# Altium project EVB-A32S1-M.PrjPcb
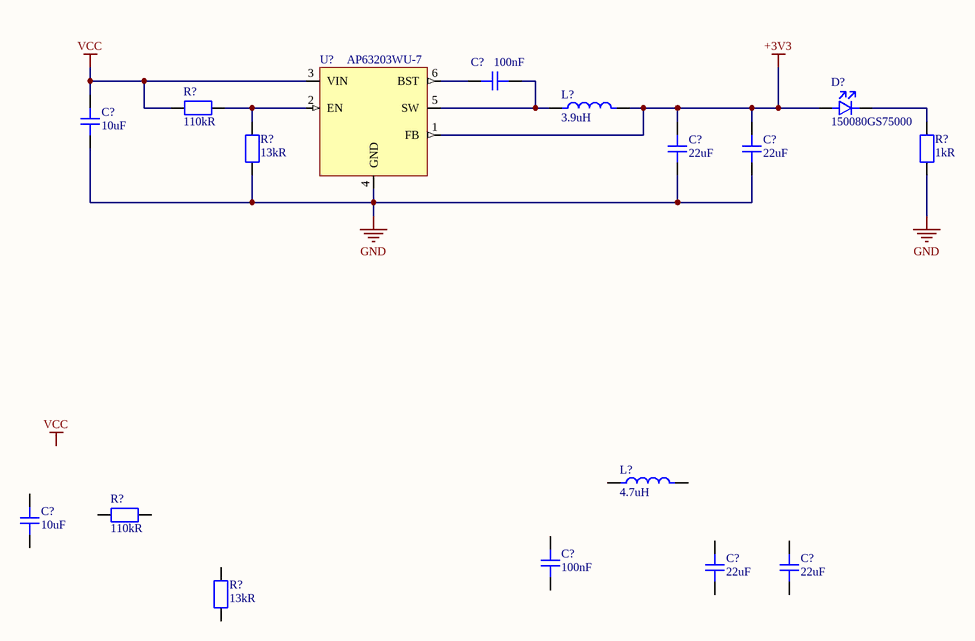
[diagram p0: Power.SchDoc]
DrawnBy: Dennis C. M.; CompanyName: Dennis Micro Computers; Title: EVB-A32S1-M
1 sheet, 17 parts. Net scope: global (net labels, ports and power ports of the same name join across sheets).

## Sheet Power.SchDoc: EVB-A32S1-M
size A4; SheetNumber: 1; SheetTotal: 1

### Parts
(Parts that share a designator on the sheet are numbered #1, #2 ... from top to bottom, then left to right.)
C?#1  value 100nF  [CAP_0402_A]  (hidden comment: CC0402MRX5R6BB104)
C?#2  value 10uF  [CAP_0805_A]  (hidden comment: CC0805KRX5R7BB106)
C?#3  value 22uF  [CAP_0805_A]  (hidden comment: CC0805MKX5R6BB226)
C?#4  value 22uF  [CAP_0805_A]  (hidden comment: CC0805MKX5R6BB226)
C?#5  value 10uF  [CAP_0805_A]  (hidden comment: CC0805KRX5R7BB106)
C?#6  value 100nF  [CAP_0402_A]  (hidden comment: CC0402MRX5R6BB104)
C?#7  value 22uF  [CAP_0805_A]  (hidden comment: CC0805MKX5R6BB226)
C?#8  value 22uF  [CAP_0805_A]  (hidden comment: CC0805MKX5R6BB226)
D?  150080GS75000  [LED_0805_A]
L?#1  value 3.9uH  [1255AY-XXXX=P3-Footprint-1]  (hidden comment: 1255AY-3R9N=P3)
L?#2  value 4.7uH  [1255AY-XXXX=P3-Footprint-1]  (hidden comment: 1255AY-4R7M=P3)
R?#1  value 110kR  [RES_0402_A]  (hidden comment: RC0402FR-07110KL)
R?#2  value 13kR  [RES_0402_A]  (hidden comment: RC0402FR-0713KL)
R?#3  value 1kR  [RES_0402_A]  (hidden comment: RC0402FR-071KL)
R?#4  value 110kR  [RES_0402_A]  (hidden comment: RC0402FR-07110KL)
R?#5  value 13kR  [RES_0402_A]  (hidden comment: RC0402FR-0713KL)
U?  AP63203WU-7  [TSOT-23-6]

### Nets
+3V3: C?#3.2 C?#4.2 D?.1 L?#1.2 U?.1(FB)
GND: C?#2.1 C?#3.1 C?#4.1 R?#2.1 R?#3.1 U?.4(GND)
VCC: C?#2.2 R?#1.2 U?.3(VIN)
NetC?#1_1: C?#1.1 L?#1.1 U?.5(SW)
NetC?#1_2: C?#1.2 U?.6(BST)
NetD?_2: D?.2 R?#3.2
NetR?#1_1: R?#1.1 R?#2.2 U?.2(EN)

Not connected (* = marked no-connect by the designer): C?#5 1 2; C?#6 1 2; C?#7 1 2; C?#8 1 2; L?#2 1 2; R?#4 1 2; R?#5 1 2

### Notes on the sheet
- Labels drawn without touching a wire or pin: VCC

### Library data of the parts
C?#1 C?#6 = CMP-001-00009-5: Multilayer Ceramic Capacitor, 0.1 uF, 25 V, ± 20%, X7R, 0402 [1005 Metric]; Dielectric: X5R; Temperature Coefficient: 30ppm/°C; Voltage Rating: 10V
C?#2 C?#5 = CMP-001-00018-1: 0805 10 uF 16 V ±10% Tolerance X5R Multilayer Ceramic Chip Capacitor; Voltage Rating (DC): 16V
C?#3 C?#4 C?#7 C?#8 = CMP-001-00014-3: Multilayer Ceramic Capacitor, 22 uF, 10 V, ± 20%, X5R, 0805 [2012 Metric]; Voltage Rating (DC): 10V
D? = CMP-007-00000-1: WURTH ELEKTRONIK - 150080GS75000 - LED, Green, SMD, 0805, 30 mA, 3.2 V, 520 nm; Forward Current: 30mA; Forward Voltage: 3.2V; Luminous Intensity: 450mcd; Max Reverse Voltage (DC): 5V; Lens Transparency: Clear; Power Dissipation: 105mW; Lens Style: Clear,Flat,Rectangular; Lens Size: 1.25mm; Viewing Angle: 140°; Test Current: 20mA; Dominant Wavelength: 520nm; Lens Color: Colorless
L?#1 = CMP-006-00002-1: Inductor Power Shielded Wirewound 3.9uH 30% 100KHz Ferrite 4.2A 0.0264Ohm DCR 2424 T/R; DC Resistance (DCR): 26.4mR; Saturation Current: 4.7A
L?#2 = CMP-006-00001-4: Inductor Power Shielded Wirewound 4.7uH 20% 100KHz Ferrite 4A 0.0276Ohm DCR 2424 T/R; DC Resistance (DCR): 27.6mR; Current Rating: 4.5A
R?#1 R?#4 = CMP-009-00000-5: SMD Chip Resistor, 110 kOhm, ± 1%, 63 mW, 0402 [1005 Metric], Thick Film, General Purpose; Max Power Dissipation: 63mW; Voltage Rating (DC): 50V; Temperature Coefficient: 100ppm/°C
R?#2 R?#5 = CMP-009-00001-5: SMD Chip Resistor, 13 kOhm, ± 1%, 63 mW, 0402 [1005 Metric], Thick Film, General Purpose; Temperature Coefficient: 100ppm/°C; Voltage Rating: 50V; Max Power Dissipation: 63mW; Power Rating: 62.5mW
R?#3 = CMP-009-00002-5: SMD Chip Resistor, 1 kOhm, ± 1%, 62.5 mW, 0402 [1005 Metric], Thick Film, General Purpose; Temperature Coefficient: 100ppm/°C; Voltage Rating (AC): 50V; Power Rating: 62.5mW; Max Power Dissipation: 63mW
U? = CMP-019-00004-4: AP63203 Series 3.3 V 2 A SMT Fixed Low IQ Synchronous Buck - TSOT-26; Max Duty Cycle: 100%; Output Voltage: 3.3V; Number of Outputs: 1; Max Supply Voltage: 32V; Switching Frequency: 1.1MHz; Min Supply Voltage: 3.8V; Nominal Supply Current: 22uA; Output Current: 2A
